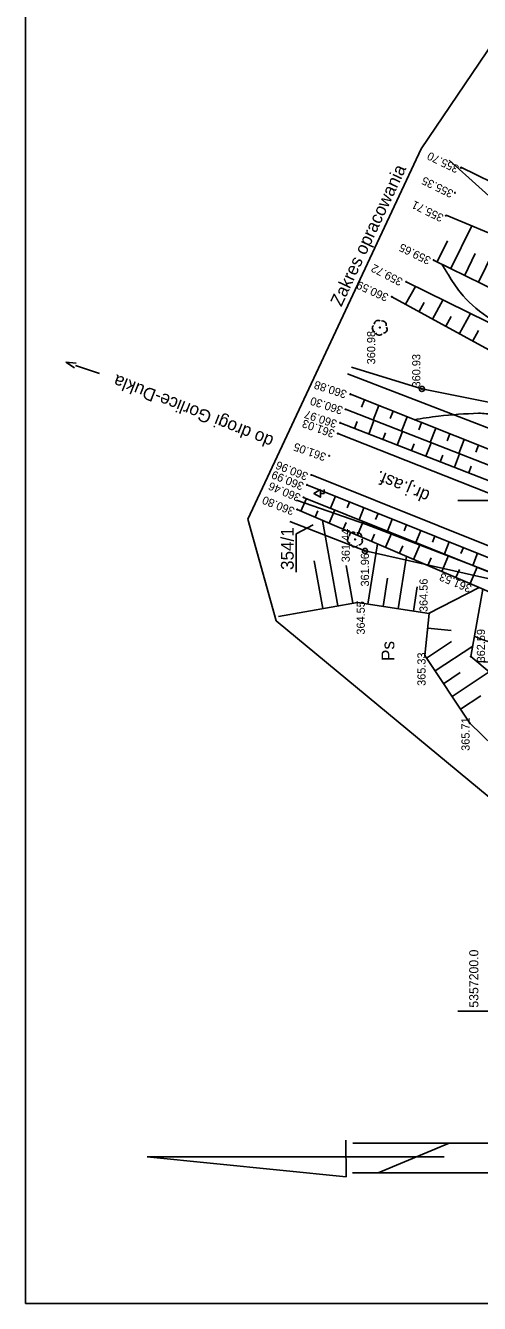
# Model space of a CAD drawing. Extents: x 4635329 to 4651863, y 5356628 to 5367582.
# Drawn here: x 4651092.2 to 4651136.6, y 5356627.7 to 5356752.8 of the extents above; entities that cross this region are included whole.
import ezdxf

# ---------------------------------------------------------------- set-up
doc = ezdxf.new("R2010")
doc.units = 0
for name, color, linetype in [('Level 1', 7, 'Continuous'), ('Level 12', 7, 'Continuous'), ('Level 13', 7, 'Continuous'), ('Level 20', 7, 'Continuous'), ('Level 21', 7, 'Continuous'), ('Level 24', 7, 'Continuous'), ('Level 4', 7, 'Continuous'), ('Level 44', 7, 'Continuous'), ('Level 45', 7, 'Continuous'), ('Level 46', 7, 'Continuous'), ('Level 48', 7, 'Continuous'), ('Level 5', 7, 'Continuous'), ('Level 50', 7, 'Continuous'), ('Level 55', 7, 'Continuous'), ('Level 58', 7, 'Continuous'), ('Level 6', 7, 'Continuous'), ('Level 60', 7, 'Continuous'), ('Level 7', 7, 'Continuous')]:
    doc.layers.add(name, color=color, linetype=linetype)

msp = doc.modelspace()

# ---------------------------------------------------------------- linework, layer by layer
at = {"layer": 'Level 1'}
for p, q in [((4651142.12, 5356757.36), (4651130.91, 5356740.76)), ((4651130.91, 5356740.76), (4651113.93, 5356704.5)), ((4651113.93, 5356704.5), (4651116.72, 5356694.56)), ((4651116.72, 5356694.56), (4651150.17, 5356666.83))]:
    msp.add_line(p, q, dxfattribs=at)
at = {"layer": 'Level 13'}
for p, q in [((4651123.55, 5356640.12), (4651123.54, 5356643.73)), ((4651124.21, 5356643.43), (4651139.86, 5356643.43)), ((4651126.69, 5356640.5), (4651133.64, 5356643.43)), ((4651104.09, 5356642.07), (4651133.16, 5356642.07)), ((4651104.09, 5356642.07), (4651123.55, 5356640.12)), ((4651124.17, 5356640.5), (4651139.82, 5356640.5))]:
    msp.add_line(p, q, dxfattribs=at)
msp.add_lwpolyline([(4651092.18, 5356627.73), (4651092.18, 5356813.36), (4651331.2, 5356813.36), (4651331.2, 5356627.73)], close=True, dxfattribs=at)
at = {"layer": 'Level 20'}
for points in [[(4651122.76, 5356712.89), (4651146.69, 5356703.43), (4651159.57, 5356698.46), (4651170.21, 5356694.07), (4651178.9, 5356691.33), (4651182.66, 5356690.55), (4651186, 5356690.06), (4651193.46, 5356690.01), (4651201.86, 5356691.05)], [(4651201.46, 5356686.17), (4651194.04, 5356685.46), (4651185.49, 5356685.02), (4651181.21, 5356685.66), (4651178.32, 5356686.25), (4651168.15, 5356689.59), (4651157.76, 5356693.69), (4651144.9, 5356698.92), (4651120.16, 5356708.84)]]:
    msp.add_lwpolyline(points, dxfattribs=at)
at = {"layer": 'Level 21'}
for p, q in [((4651096.98, 5356719.33), (4651096.12, 5356719.89)), ((4651096.12, 5356719.89), (4651097.14, 5356719.8)), ((4651099.43, 5356718.76), (4651097.06, 5356719.57))]:
    msp.add_line(p, q, dxfattribs=at)
at = {"layer": 'Level 24'}
for p, q in [((4651121.41, 5356707.04), (4651121.05, 5356707.04)), ((4651121.41, 5356707.41), (4651121.41, 5356707.04))]:
    msp.add_line(p, q, dxfattribs=at)
msp.add_lwpolyline([(4651121.05, 5356707.41), (4651121.05, 5356706.66), (4651120.41, 5356707.04)], close=True, dxfattribs=at)
at = {"layer": 'Level 4'}
for p, q in [((4651133.66, 5356739.65), (4651155.67, 5356719.83)), ((4651124.1, 5356719.38), (4651130.98, 5356717.26)), ((4651159.61, 5356704.89), (4651123.69, 5356718.75)), ((4651130.98, 5356717.26), (4651177.54, 5356707.98)), ((4651125.56, 5356703.99), (4651118.71, 5356706.36)), ((4651125.41, 5356701.4), (4651118.05, 5356704.28)), ((4651118.67, 5356703.09), (4651120.34, 5356703.97)), ((4651169.9, 5356686.91), (4651125.56, 5356703.99)), ((4651118.67, 5356699.33), (4651118.67, 5356703.09)), ((4651174.83, 5356690.31), (4651125.41, 5356701.4))]:
    msp.add_line(p, q, dxfattribs=at)
at = {"layer": 'Level 44'}
for centre in [(4651134.8, 5356738.92), (4651134.22, 5356736.47), (4651133.32, 5356734.23), (4651132.13, 5356729.88), (4651129.44, 5356727.75), (4651128.04, 5356726.29), (4651126.87, 5356723.27), (4651123.98, 5356716.74), (4651130.98, 5356717.26), (4651123.5, 5356715.27), (4651122.98, 5356713.94), (4651122.76, 5356712.89), (4651121.9, 5356710.71), (4651120.16, 5356708.84), (4651119.73, 5356707.87), (4651119.4, 5356706.65), (4651118.78, 5356705.46), (4651124.44, 5356702.54), (4651125.41, 5356701.4), (4651124.67, 5356696.36), (4651131.7, 5356695.27), (4651131.28, 5356691.16), (4651135.76, 5356691.07), (4651135.67, 5356684.53)]:
    msp.add_circle(centre, 0.04, dxfattribs=at)
at = {"layer": 'Level 46'}
for points in [[(4651145.84, 5356723.15), (4651143.52, 5356723.03), (4651139.88, 5356723.15), (4651137.33, 5356724.36), (4651134.73, 5356726.73), (4651133.58, 5356728.42), (4651132.92, 5356729.49)], [(4651130.22, 5356714.25), (4651132.6, 5356714.6), (4651136.53, 5356714.89)], [(4651136.53, 5356714.89), (4651137.27, 5356714.84), (4651138.74, 5356714.65)], [(4651156.76, 5356687.52), (4651156.25, 5356687.7), (4651149.03, 5356687.58), (4651145.81, 5356689.82), (4651143.27, 5356691.04), (4651138.78, 5356692.07), (4651136.17, 5356693.04), (4651136.12, 5356693.06)], [(4651145.72, 5356683.84), (4651144.9, 5356684.67), (4651142.42, 5356688.31), (4651139.32, 5356689.88), (4651137.2, 5356690.55), (4651136.38, 5356690.55)]]:
    msp.add_spline(points, degree=3, dxfattribs=at)
at = {"layer": 'Level 48'}
for p, q in [((4651133.82, 5356729.05), (4651135.87, 5356733.22)), ((4651132.47, 5356729.71), (4651133.48, 5356731.76)), ((4651136.51, 5356727.73), (4651138.64, 5356732.06)), ((4651135.17, 5356728.39), (4651136.21, 5356730.51)), ((4651129.38, 5356725.55), (4651130.34, 5356727.3)), ((4651130.7, 5356724.83), (4651131.19, 5356725.74)), ((4651132.02, 5356724.11), (4651133.03, 5356725.97)), ((4651133.33, 5356723.4), (4651133.86, 5356724.35)), ((4651134.65, 5356722.68), (4651135.73, 5356724.65)), ((4651135.97, 5356721.96), (4651136.52, 5356722.97)), ((4651125.37, 5356716.18), (4651125.08, 5356715.47)), ((4651126.76, 5356715.63), (4651126.2, 5356714.21)), ((4651124.37, 5356713.39), (4651124.63, 5356714.06)), ((4651125.77, 5356712.85), (4651126.29, 5356714.18)), ((4651128.16, 5356715.08), (4651127.88, 5356714.37)), ((4651129.55, 5356714.52), (4651128.99, 5356713.12)), ((4651130.95, 5356713.97), (4651130.67, 5356713.27)), ((4651127.17, 5356712.31), (4651127.43, 5356712.97)), ((4651128.57, 5356711.76), (4651129.08, 5356713.08)), ((4651132.34, 5356713.41), (4651131.79, 5356712.03)), ((4651133.73, 5356712.86), (4651133.46, 5356712.17)), ((4651129.97, 5356711.22), (4651130.22, 5356711.88)), ((4651131.36, 5356710.68), (4651131.88, 5356711.99)), ((4651135.13, 5356712.3), (4651134.58, 5356710.94)), ((4651136.52, 5356711.75), (4651136.25, 5356711.07)), ((4651132.76, 5356710.13), (4651133.02, 5356710.79)), ((4651134.16, 5356709.59), (4651134.67, 5356710.9)), ((4651135.56, 5356709.05), (4651135.81, 5356709.7)), ((4651119.14, 5356705.3), (4651119.67, 5356706.54)), ((4651122.51, 5356706.75), (4651122.04, 5356705.58)), ((4651120.52, 5356704.71), (4651120.79, 5356705.34)), ((4651121.9, 5356704.12), (4651122.46, 5356705.42)), ((4651123.9, 5356706.19), (4651123.67, 5356705.61)), ((4651125.29, 5356705.63), (4651124.83, 5356704.46)), ((4651126.69, 5356705.08), (4651126.45, 5356704.49)), ((4651122.75, 5356696.02), (4651121.26, 5356704.39)), ((4651123.28, 5356703.53), (4651123.57, 5356704.19)), ((4651124.66, 5356702.94), (4651125.24, 5356704.3)), ((4651128.08, 5356704.52), (4651127.61, 5356703.35)), ((4651129.47, 5356703.96), (4651129.24, 5356703.38)), ((4651126.04, 5356702.35), (4651126.34, 5356703.04)), ((4651127.42, 5356701.76), (4651128.03, 5356703.18)), ((4651130.86, 5356703.4), (4651130.39, 5356702.23)), ((4651132.26, 5356702.85), (4651132.02, 5356702.26)), ((4651125.7, 5356696.2), (4651126.62, 5356702.1)), ((4651128.8, 5356701.17), (4651129.11, 5356701.89)), ((4651130.17, 5356700.58), (4651130.81, 5356702.06)), ((4651133.65, 5356702.29), (4651133.18, 5356701.11)), ((4651135.04, 5356701.73), (4651134.8, 5356701.14)), ((4651121.27, 5356695.76), (4651120.44, 5356700.43)), ((4651128.67, 5356695.74), (4651129.46, 5356700.88)), ((4651131.55, 5356699.98), (4651131.88, 5356700.74)), ((4651132.93, 5356699.39), (4651133.6, 5356700.94)), ((4651136.43, 5356701.17), (4651135.96, 5356699.99)), ((4651124.22, 5356696.28), (4651123.57, 5356699.98)), ((4651134.31, 5356698.8), (4651134.65, 5356699.59)), ((4651135.69, 5356698.21), (4651136.38, 5356699.82)), ((4651127.19, 5356695.97), (4651127.61, 5356698.73)), ((4651130.15, 5356695.51), (4651130.52, 5356697.89)), ((4651131.63, 5356695.28), (4651136.58, 5356697.83)), ((4651131.55, 5356693.84), (4651133.86, 5356693.6)), ((4651131.44, 5356690.9), (4651133.88, 5356692.52)), ((4651132.27, 5356689.65), (4651135.95, 5356692.09)), ((4651133.1, 5356688.4), (4651134.73, 5356689.49)), ((4651133.93, 5356687.15), (4651137.56, 5356689.56)), ((4651134.76, 5356685.9), (4651136.76, 5356687.23))]:
    msp.add_line(p, q, dxfattribs=at)
for points in [[(4651181.95, 5356698.96), (4651174.7, 5356705.05), (4651165.21, 5356711.24), (4651153.54, 5356719.46), (4651148.11, 5356722.04), (4651132.13, 5356729.88)], [(4651129.44, 5356727.75), (4651147.42, 5356718.89), (4651153.08, 5356712.62)], [(4651153.08, 5356712.62), (4651128.04, 5356726.29)], [(4651123.98, 5356716.74), (4651147.83, 5356707.26), (4651160.98, 5356701.96), (4651171.65, 5356698.2), (4651179.5, 5356694.9)], [(4651179.49, 5356693.39), (4651171.32, 5356696.75), (4651160.5, 5356700.67), (4651147.54, 5356705.88), (4651123.5, 5356715.27)], [(4651122.98, 5356713.94), (4651147.04, 5356704.59), (4651160, 5356699.55), (4651170.76, 5356695.24), (4651179, 5356692.39)], [(4651119.73, 5356707.87), (4651145.11, 5356697.7), (4651157.44, 5356692.75), (4651164.5, 5356690.1)], [(4651119.4, 5356706.65), (4651144.58, 5356696.53), (4651156.92, 5356691.73), (4651164.13, 5356689.01)], [(4651163.82, 5356687.91), (4651156.33, 5356689.96), (4651143.75, 5356694.65), (4651136.83, 5356697.73), (4651118.78, 5356705.46)], [(4651153.2, 5356678.11), (4651145.71, 5356682.73), (4651135.76, 5356691.07), (4651136.95, 5356697.67)], [(4651150.63, 5356670.01), (4651135.67, 5356684.53), (4651131.28, 5356691.16), (4651131.7, 5356695.27), (4651124.67, 5356696.36), (4651116.94, 5356694.99)]]:
    msp.add_lwpolyline(points, dxfattribs=at)
at = {"layer": 'Level 50'}
for p, q in [((4651147.74, 5356732.62), (4651134.8, 5356738.99)), ((4651145.69, 5356729.1), (4651133.35, 5356734.28))]:
    msp.add_line(p, q, dxfattribs=at)
at = {"layer": 'Level 55'}
for centre in [(4651126.87, 5356723.27), (4651124.44, 5356702.53)]:
    msp.add_circle(centre, 0.045, dxfattribs=at)
for centre, start, end in [((4651126.69, 5356723.6), 58.348, 178.132), ((4651127.12, 5356723.54), 346.3906, 106.042), ((4651126.5, 5356723.2), 130.3488, 250.1306), ((4651126.81, 5356722.9), 202.4389, 322.0902), ((4651127.2, 5356723.1), 274.3875, 34.0933), ((4651124.07, 5356702.47), 130.3488, 250.1306), ((4651124.26, 5356702.86), 58.348, 178.132), ((4651124.7, 5356702.8), 346.3906, 106.042), ((4651124.78, 5356702.37), 274.3875, 34.0933), ((4651124.39, 5356702.16), 202.4389, 322.0902)]:
    msp.add_arc(centre, 0.375, start, end, dxfattribs=at)
at = {"layer": 'Level 60'}
for p, q in [((4651139.51, 5356706.35), (4651134.51, 5356706.35)), ((4651139.51, 5356656.35), (4651134.51, 5356656.35))]:
    msp.add_line(p, q, dxfattribs=at)
at = {"layer": 'Level 7'}
for centre in [(4651130.98, 5356717.26), (4651125.4, 5356701.4)]:
    msp.add_circle(centre, 0.25, dxfattribs=at)

# ---------------------------------------------------------------- texts
at = {"layer": 'Level 12'}
msp.add_text('Ps', height=1.25, rotation=90, dxfattribs=at).set_placement((4651128.28, 5356690.63))
at = {"layer": 'Level 21'}
for s, rotation, p in [('do drogi Gorlice-Dukla', 158.422, (4651116.56, 5356712.58)), ('dr.j.asf. ', 157.5793, (4651131.86, 5356707.22))]:
    msp.add_text(s, height=1.25, rotation=rotation, dxfattribs=at).set_placement(p)
at = {"layer": 'Level 45'}
for s, rotation, p in [('355.70', 153.9505, (4651134.69, 5356739.07)), ('355.35', 153.9505, (4651134.15, 5356736.65)), ('355.71', 153.9505, (4651133.18, 5356734.29)), ('359.65', 153.9505, (4651131.94, 5356730.11)), ('359.72', 152.7145, (4651129.19, 5356728.02)), ('360.59', 155.6101, (4651127.79, 5356726.51)), ('360.98', 90, (4651126.41, 5356719.67)), ('360.93', 90, (4651130.83, 5356717.41)), ('360.88', 161.9955, (4651123.7, 5356717.07)), ('360.30', 162.0802, (4651123.32, 5356715.5)), ('360.97', 161.5715, (4651122.75, 5356714.17)), ('361.03', 160.4275, (4651122.52, 5356713.2)), ('361.05', 160.4198, (4651121.68, 5356710.92)), ('360.96', 158.1344, (4651119.92, 5356709.01)), ('360.99', 157.4884, (4651119.5, 5356708.04)), ('360.46', 157.2991, (4651119.19, 5356706.92)), ('360.80', 158.3808, (4651118.59, 5356705.6)), ('361.44', 90, (4651123.92, 5356700.3)), ('361.96', 90, (4651125.8, 5356697.92)), ('361.53', 157.2135, (4651135.93, 5356698.02)), ('364.56', 90, (4651131.54, 5356695.42)), ('364.55', 90, (4651125.39, 5356693.21)), ('362.59', 90, (4651137.16, 5356690.49)), ('365.33', 90, (4651131.34, 5356688.19)), ('365.71', 90, (4651135.65, 5356681.83))]:
    msp.add_text(s, height=0.8, rotation=rotation, dxfattribs=at).set_placement(p)
at = {"layer": 'Level 5'}
msp.add_text('354/1', height=1.25, rotation=90, dxfattribs=at).set_placement((4651118.43, 5356699.54))
at = {"layer": 'Level 58'}
msp.add_text(' 5357200.0 ', height=0.9, rotation=90, dxfattribs=at).set_placement((4651136.51, 5356656.35))
at = {"layer": 'Level 6'}
msp.add_text('Zakres opracowania', height=1.25, rotation=64.9038, dxfattribs=at).set_placement((4651123.09, 5356725.24))

doc.saveas('drawing.dxf')
